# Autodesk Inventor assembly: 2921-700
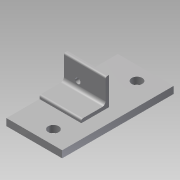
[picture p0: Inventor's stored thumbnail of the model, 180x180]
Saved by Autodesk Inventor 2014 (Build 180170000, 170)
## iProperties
Company: NHTSA/VRTC
Created: 2012-11
Part Number: 2921-700
Document SubType Name: Assembly
Designer: Mike Vanvoorhis
Project: CHILD SIDE IMPACT SLED
Description: LIGHT TRAP MOUNT ASSEMBLY
Author: Dave Walker
Title: Light Trap Mount Assembly
Subject: Child Side Impact Sled
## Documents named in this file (3)
- B:\VRTC_DWG\BIO\Non-P572\Child Side-Frontal Impact Sled\Side Impact Sled\Light Trap Mount Assembly.iam
- B:\VRTC_DWG\BIO\Non-P572\Child Side-Frontal Impact Sled\Side Impact Sled\Light Trap Base Plate.ipt
- B:\VRTC_DWG\BIO\Non-P572\Child Side-Frontal Impact Sled\Side Impact Sled\Light Trap Bracket.ipt
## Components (2 placed, 2 different names)
1. Light Trap Base Plate:1 — Mate:1, Flush:1, Mate:2
2. Light Trap Bracket:1 — Mate:1, Flush:1, Mate:2
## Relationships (3: Mate 2, Flush 1)
- Mate:1: Light Trap Base Plate:1 ↔ Light Trap Bracket:1
- Flush:1: Light Trap Base Plate:1 ↔ Light Trap Bracket:1
- Mate:2: Light Trap Base Plate:1 ↔ Light Trap Bracket:1
